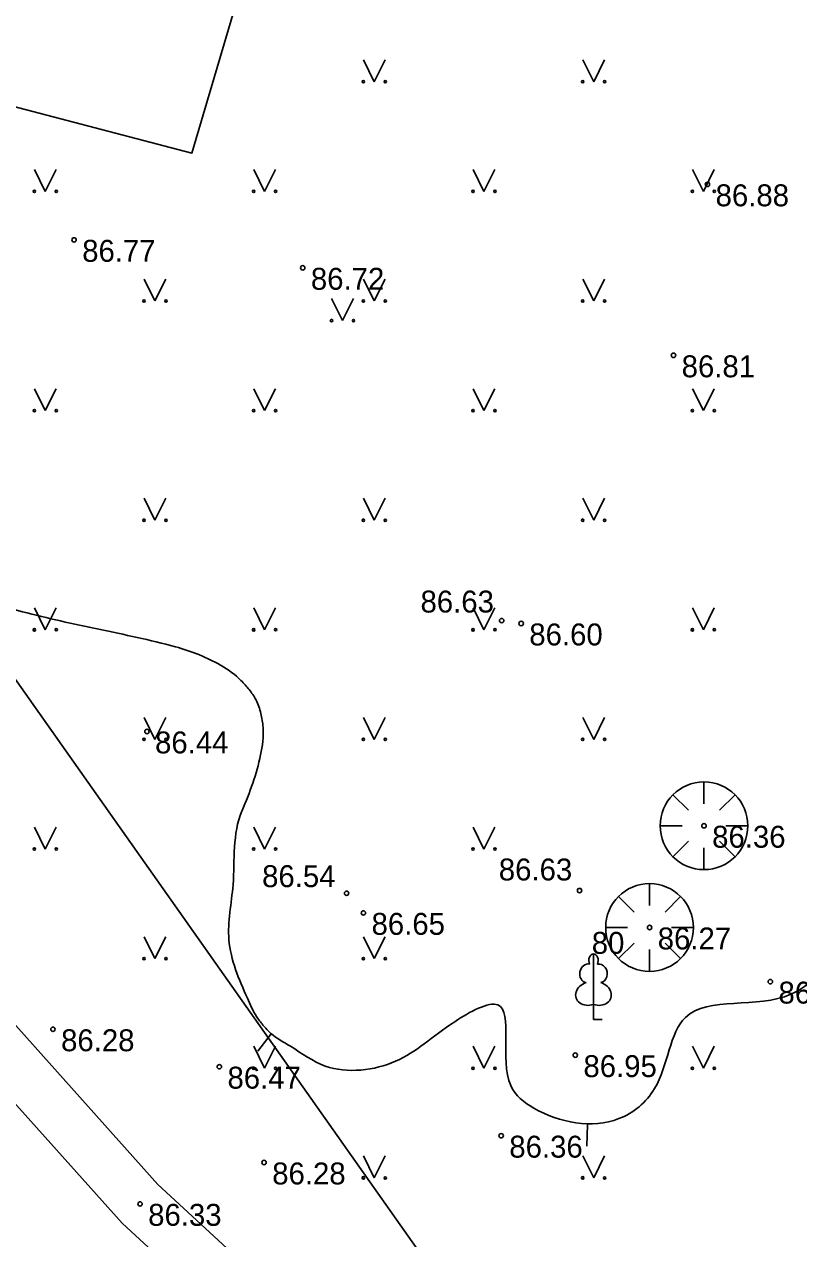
# Model space of a CAD drawing. Extents: x 576692 to 577659, y 273254 to 273799.
# Drawn here: x 577474.52 to 577492.17, y 273401.11 to 273428.81 of the extents above; entities that cross this region are included whole.
import ezdxf

# ---------------------------------------------------------------- set-up
doc = ezdxf.new("R2010")
doc.units = 0
for name, color, linetype in [('APGR_SARK_####_####_#', 7, 'Continuous'), ('CELI_TAKA_####_####_#', 7, 'Continuous'), ('ELEK_ELEM_####_####_#', 7, 'Continuous'), ('ELEK_VADP_VSPR_####_#', 7, 'Continuous'), ('GEOD_SITP_####_TKST_#', 7, 'Continuous'), ('HIDT_REZV_####_TKST_#', 7, 'Continuous'), ('LKAN_ELEM_PAST_TKST_#', 7, 'Continuous'), ('RELJ_ELEM_####_####_#', 7, 'Continuous'), ('TERT_KRND_####_####_#', 7, 'Continuous')]:
    doc.layers.add(name, color=color, linetype=linetype)

msp = doc.modelspace()

# ---------------------------------------------------------------- linework, layer by layer
at = {"layer": 'CELI_TAKA_####_####_#'}
msp.add_lwpolyline([(577456.559, 273431.587), (577478.341, 273425.873), (577486.021, 273451.871)], dxfattribs=at)
at = {"layer": 'ELEK_ELEM_####_####_#'}
for points in [[(577431.446, 273433.794), (577439.287, 273433.5), (577443.622, 273433.428), (577448.64, 273432.011), (577452.453, 273428.814), (577456.965, 273425.862), (577459.224, 273423.687), (577462.829, 273419.732), (577467.389, 273414.302), (577473.49, 273406.901), (577477.566, 273402.347)], [(577431.402, 273432.594), (577439.255, 273432.3), (577443.446, 273432.23), (577448.066, 273430.927), (577451.737, 273427.848), (577456.213, 273424.92), (577458.364, 273422.849), (577461.925, 273418.942), (577466.467, 273413.534), (577472.58, 273406.119), (577476.752, 273401.465)], [(577504.541, 273374.158), (577501.597, 273377.211), (577498.583, 273380.418), (577495.285, 273383.979), (577488.811, 273390.578), (577482.679, 273397.624), (577477.566, 273402.347)], [(577526.515, 273350.26), (577524.694, 273352.062), (577522.615, 273353.988), (577519.694, 273357.008), (577515.984, 273361.423), (577511.699, 273364.615), (577508.487, 273368.121), (577504.539, 273372.31), (577503.653, 273373.35), (577500.727, 273376.383), (577497.705, 273379.6), (577494.417, 273383.151), (577487.929, 273389.764), (577481.817, 273396.786), (577476.752, 273401.465)]]:
    msp.add_lwpolyline(points, dxfattribs=at)
at = {"layer": 'ELEK_VADP_VSPR_####_#'}
for centre in [(577498.474, 273401.727), (577500.973, 273398.95)]:
    msp.add_circle(centre, 50, dxfattribs=at)
at = {"layer": 'GEOD_SITP_####_TKST_#'}
for p, q in [((577479.845, 273405.393), (577480.152, 273405.787)), ((577487.343, 273403.22), (577487.356, 273403.719))]:
    msp.add_line(p, q, dxfattribs=at)
msp.add_spline([(577454.178, 273425.217), (577454.308, 273425.114), (577454.493, 273424.971), (577454.62, 273424.866), (577455.044, 273424.676), (577455.301, 273424.603), (577455.571, 273424.558), (577455.836, 273424.51), (577456.073, 273424.433), (577456.101, 273424.407), (577456.108, 273424.368), (577456.072, 273424.266), (577455.897, 273424.082), (577454.953, 273423.781), (577454.728, 273423.789), (577454.501, 273423.848), (577454.046, 273424.041), (577453.591, 273424.198), (577453.365, 273424.212), (577453.141, 273424.156), (577452.984, 273424.037), (577452.875, 273423.866), (577452.809, 273423.622), (577452.809, 273423.365), (577452.82, 273423.112), (577452.784, 273422.885), (577452.591, 273422.638), (577452.296, 273422.423), (577452.016, 273422.211), (577451.87, 273421.969), (577451.868, 273421.809), (577451.905, 273421.63), (577452.091, 273421.308), (577452.199, 273421.214), (577452.313, 273421.13), (577452.425, 273421.047), (577452.528, 273420.953), (577453.421, 273419.977), (577453.991, 273419.194), (577454.233, 273418.572), (577454.561, 273417.259), (577454.233, 273415.67), (577454.247, 273413.424), (577457.749, 273413.769), (577459.551, 273413.744), (577460.44, 273413.405), (577461.024, 273413.111), (577461.288, 273413.023), (577461.424, 273413.007), (577461.556, 273413.017), (577461.886, 273413.28), (577461.991, 273413.634), (577462.057, 273413.988), (577462.102, 273414.699), (577461.586, 273415.987), (577461.367, 273416.403), (577461.58, 273417.646), (577461.746, 273417.982), (577461.865, 273418.292), (577461.938, 273418.446), (577461.995, 273418.601), (577462.275, 273418.9), (577462.703, 273419.018), (577462.927, 273419.008), (577463.153, 273418.98), (577463.588, 273418.836), (577464.266, 273418.445), (577464.558, 273418.283), (577465.743, 273417.759), (577466.956, 273417.318), (577469.44, 273416.609), (577471.963, 273416.021), (577473.224, 273415.728), (577474.477, 273415.413), (577475.345, 273415.202), (577476.218, 273415.014), (577477.093, 273414.826), (577477.965, 273414.613), (577478.5, 273414.434), (577478.758, 273414.318), (577479.012, 273414.186), (577479.459, 273413.844), (577479.647, 273413.636), (577479.803, 273413.399), (577479.913, 273413.093), (577479.965, 273412.775), (577479.907, 273412.145), (577479.487, 273410.88), (577479.481, 273410.866), (577479.279, 273409.186), (577479.186, 273407.93), (577479.606, 273406.595), (577479.814, 273406.183), (577479.961, 273405.986), (577480.142, 273405.795), (577480.588, 273405.5), (577481.38, 273405.051), (577482.985, 273405.16), (577484.332, 273406.062), (577485.316, 273406.445), (577485.609, 273404.606), (577486.134, 273404.09), (577488.072, 273403.85), (577488.888, 273404.536), (577489.591, 273406.161), (577491.998, 273406.686), (577492.592, 273407.093), (577494.556, 273408.742), (577497.797, 273409.634), (577501.552, 273409.445), (577503.768, 273409.607), (577505.443, 273410.823), (577506.415, 273412.202), (577507.053, 273412.929)], degree=3, dxfattribs=at)
at = {"layer": 'LKAN_ELEM_PAST_TKST_#'}
for p, q in [((577482.25, 273428), (577482.5, 273427.5)), ((577482.5, 273427.5), (577482.75, 273428)), ((577487.25, 273428), (577487.5, 273427.5)), ((577487.5, 273427.5), (577487.75, 273428)), ((577474.75, 273425.5), (577475, 273425)), ((577475, 273425), (577475.25, 273425.5)), ((577479.75, 273425.5), (577480, 273425)), ((577480, 273425), (577480.25, 273425.5)), ((577484.75, 273425.5), (577485, 273425)), ((577485, 273425), (577485.25, 273425.5)), ((577489.75, 273425.5), (577490, 273425)), ((577490, 273425), (577490.25, 273425.5)), ((577477.25, 273423), (577477.5, 273422.5)), ((577477.5, 273422.5), (577477.75, 273423)), ((577482.25, 273423), (577482.5, 273422.5)), ((577482.5, 273422.5), (577482.75, 273423)), ((577487.25, 273423), (577487.5, 273422.5)), ((577487.5, 273422.5), (577487.75, 273423)), ((577481.525, 273422.555), (577481.775, 273422.055)), ((577481.775, 273422.055), (577482.025, 273422.555)), ((577474.75, 273420.5), (577475, 273420)), ((577475, 273420), (577475.25, 273420.5)), ((577479.75, 273420.5), (577480, 273420)), ((577480, 273420), (577480.25, 273420.5)), ((577484.75, 273420.5), (577485, 273420)), ((577485, 273420), (577485.25, 273420.5)), ((577489.75, 273420.5), (577490, 273420)), ((577490, 273420), (577490.25, 273420.5)), ((577477.25, 273418), (577477.5, 273417.5)), ((577477.5, 273417.5), (577477.75, 273418)), ((577482.25, 273418), (577482.5, 273417.5)), ((577482.5, 273417.5), (577482.75, 273418)), ((577487.25, 273418), (577487.5, 273417.5)), ((577487.5, 273417.5), (577487.75, 273418)), ((577474.75, 273415.5), (577475, 273415)), ((577475, 273415), (577475.25, 273415.5)), ((577479.75, 273415.5), (577480, 273415)), ((577480, 273415), (577480.25, 273415.5)), ((577484.75, 273415.5), (577485, 273415)), ((577485, 273415), (577485.25, 273415.5)), ((577489.75, 273415.5), (577490, 273415)), ((577490, 273415), (577490.25, 273415.5)), ((577477.25, 273413), (577477.5, 273412.5)), ((577477.5, 273412.5), (577477.75, 273413)), ((577482.25, 273413), (577482.5, 273412.5)), ((577482.5, 273412.5), (577482.75, 273413)), ((577487.25, 273413), (577487.5, 273412.5)), ((577487.5, 273412.5), (577487.75, 273413)), ((577474.75, 273410.5), (577475, 273410)), ((577475, 273410), (577475.25, 273410.5)), ((577479.75, 273410.5), (577480, 273410)), ((577480, 273410), (577480.25, 273410.5)), ((577484.75, 273410.5), (577485, 273410)), ((577485, 273410), (577485.25, 273410.5)), ((577477.25, 273408), (577477.5, 273407.5)), ((577477.5, 273407.5), (577477.75, 273408)), ((577482.25, 273408), (577482.5, 273407.5)), ((577482.5, 273407.5), (577482.75, 273408)), ((577487.496, 273406.456), (577487.496, 273406.109)), ((577487.496, 273406.109), (577487.696, 273406.109)), ((577479.75, 273405.5), (577480, 273405)), ((577480, 273405), (577480.25, 273405.5)), ((577484.75, 273405.5), (577485, 273405)), ((577485, 273405), (577485.25, 273405.5)), ((577489.75, 273405.5), (577490, 273405)), ((577490, 273405), (577490.25, 273405.5)), ((577482.25, 273403), (577482.5, 273402.5)), ((577482.5, 273402.5), (577482.75, 273403)), ((577487.25, 273403), (577487.5, 273402.5)), ((577487.5, 273402.5), (577487.75, 273403))]:
    msp.add_line(p, q, dxfattribs=at)
for points in [[(577487.496, 273407.609), (577487.496, 273406.456)], [(577487.586, 273407.377), (577487.585, 273407.378)]]:
    msp.add_lwpolyline(points, dxfattribs=at)
for centre, radius in [((577482.25, 273427.5), 0.028), ((577482.75, 273427.5), 0.0263), ((577487.25, 273427.5), 0.028), ((577487.75, 273427.5), 0.0263), ((577474.75, 273425), 0.028), ((577475.25, 273425), 0.0263), ((577479.75, 273425), 0.028), ((577480.25, 273425), 0.0263), ((577484.75, 273425), 0.028), ((577485.25, 273425), 0.0263), ((577489.75, 273425), 0.028), ((577490.25, 273425), 0.0263), ((577477.25, 273422.5), 0.028), ((577477.75, 273422.5), 0.0263), ((577482.25, 273422.5), 0.028), ((577482.75, 273422.5), 0.0263), ((577487.25, 273422.5), 0.028), ((577487.75, 273422.5), 0.0263), ((577481.525, 273422.054), 0.028), ((577482.025, 273422.054), 0.0263), ((577474.75, 273420), 0.028), ((577475.25, 273420), 0.0263), ((577479.75, 273420), 0.028), ((577480.25, 273420), 0.0263), ((577484.75, 273420), 0.028), ((577485.25, 273420), 0.0263), ((577489.75, 273420), 0.028), ((577490.25, 273420), 0.0263), ((577477.25, 273417.5), 0.028), ((577477.75, 273417.5), 0.0263), ((577482.25, 273417.5), 0.028), ((577482.75, 273417.5), 0.0263), ((577487.25, 273417.5), 0.028), ((577487.75, 273417.5), 0.0263), ((577474.75, 273415), 0.028), ((577475.25, 273415), 0.0263), ((577479.75, 273415), 0.028), ((577480.25, 273415), 0.0263), ((577484.75, 273415), 0.028), ((577485.25, 273415), 0.0263), ((577489.75, 273415), 0.028), ((577490.25, 273415), 0.0263), ((577477.25, 273412.5), 0.028), ((577477.75, 273412.5), 0.0263), ((577482.25, 273412.5), 0.028), ((577482.75, 273412.5), 0.0263), ((577487.25, 273412.5), 0.028), ((577487.75, 273412.5), 0.0263), ((577474.75, 273410), 0.028), ((577475.25, 273410), 0.0263), ((577479.75, 273410), 0.028), ((577480.25, 273410), 0.0263), ((577484.75, 273410), 0.028), ((577485.25, 273410), 0.0263), ((577477.25, 273407.5), 0.028), ((577477.75, 273407.5), 0.0263), ((577482.25, 273407.5), 0.028), ((577482.75, 273407.5), 0.0263), ((577479.75, 273405), 0.028), ((577480.25, 273405), 0.0263), ((577484.75, 273405), 0.028), ((577485.25, 273405), 0.0263), ((577489.75, 273405), 0.028), ((577490.25, 273405), 0.0263), ((577482.25, 273402.5), 0.028), ((577482.75, 273402.5), 0.0263), ((577487.25, 273402.5), 0.028), ((577487.75, 273402.5), 0.0263)]:
    msp.add_circle(centre, radius, dxfattribs=at)
for centre, major_axis, ratio, start_param, end_param in [((577487.368, 273407.164), (-0.039, -0.212), 0.861323, 3.141593, 6.283185), ((577487.496, 273407.459), (0, -0.15), 0.707107, 3.14537, 5.287485), ((577487.496, 273407.459), (0, -0.15), 0.707107, 0.995701, 3.137816), ((577487.624, 273407.164), (0.039, -0.212), 0.861323, 0, 3.141593), ((577487.406, 273406.702), (0.307, 0.095), 0.814445, 1.570796, 4.752015), ((577487.586, 273406.702), (-0.307, 0.095), 0.814445, 1.531171, 4.712389)]:
    msp.add_ellipse(centre, major_axis=major_axis, ratio=ratio, start_param=start_param, end_param=end_param, dxfattribs=at)
at = {"layer": 'RELJ_ELEM_####_####_#'}
for p, q in [((577490.015, 273411.53), (577490.015, 273411.03)), ((577489.308, 273411.237), (577489.662, 273410.883)), ((577490.369, 273410.883), (577490.722, 273411.237)), ((577489.015, 273410.53), (577489.515, 273410.53)), ((577490.515, 273410.53), (577491.015, 273410.53)), ((577489.308, 273409.823), (577489.662, 273410.176)), ((577490.369, 273410.176), (577490.722, 273409.823)), ((577490.015, 273410.03), (577490.015, 273409.53)), ((577488.774, 273409.21), (577488.774, 273408.71)), ((577488.067, 273408.917), (577488.421, 273408.563)), ((577489.128, 273408.563), (577489.481, 273408.917)), ((577487.774, 273408.21), (577488.274, 273408.21)), ((577489.274, 273408.21), (577489.774, 273408.21)), ((577488.067, 273407.503), (577488.421, 273407.856)), ((577488.774, 273407.71), (577488.774, 273407.21)), ((577489.128, 273407.856), (577489.481, 273407.503))]:
    msp.add_line(p, q, dxfattribs=at)
for centre, radius in [((577490.094, 273425.16), 0.05), ((577475.655, 273423.894), 0.05), ((577480.868, 273423.256), 0.05), ((577489.32, 273421.26), 0.05), ((577485.403, 273415.211), 0.05), ((577485.847, 273415.144), 0.05), ((577477.316, 273412.681), 0.05), ((577490.015, 273410.53), 1), ((577490.015, 273410.53), 0.05), ((577481.867, 273408.992), 0.05), ((577487.178, 273409.053), 0.05), ((577488.774, 273408.21), 1), ((577482.251, 273408.543), 0.05), ((577488.774, 273408.21), 0.05), ((577491.527, 273406.975), 0.05), ((577475.174, 273405.888), 0.05), ((577487.081, 273405.298), 0.05), ((577478.967, 273405.035), 0.05), ((577485.391, 273403.461), 0.05), ((577479.987, 273402.85), 0.05), ((577477.159, 273401.906), 0.05)]:
    msp.add_circle(centre, radius, dxfattribs=at)
at = {"layer": 'TERT_KRND_####_####_#'}
msp.add_lwpolyline([(577471.439, 273417.943), (577504.938, 273370.442), (577469.56, 273330.315), (577408.781, 273341.539), (577378.053, 273361.375), (577348.46, 273393.654), (577360.328, 273412.589)], dxfattribs=at)

# ---------------------------------------------------------------- texts
at = {"layer": 'APGR_SARK_####_####_#'}
msp.add_text(' 80', height=0.5, dxfattribs=at).set_placement((577487.271, 273407.609))
at = {"layer": 'HIDT_REZV_####_TKST_#'}
for s, p in [(' 86.88', (577490.094, 273424.66)), (' 86.77', (577475.655, 273423.394)), (' 86.72', (577480.868, 273422.756)), (' 86.81', (577489.32, 273420.76)), (' 86.63', (577483.367, 273415.394)), (' 86.60', (577485.847, 273414.644)), (' 86.44', (577477.316, 273412.181)), (' 86.36', (577490.015, 273410.03)), (' 86.54', (577479.756, 273409.131)), (' 86.63', (577485.152, 273409.283)), (' 86.65', (577482.251, 273408.043)), (' 86.27', (577488.774, 273407.71)), (' 86.59', (577491.527, 273406.475)), (' 86.28', (577475.174, 273405.388)), (' 86.95', (577487.081, 273404.798)), (' 86.47', (577478.967, 273404.535)), (' 86.36', (577485.391, 273402.961)), (' 86.28', (577479.987, 273402.35)), (' 86.33', (577477.159, 273401.406))]:
    msp.add_text(s, height=0.5, dxfattribs=at).set_placement(p)

doc.saveas('drawing.dxf')
